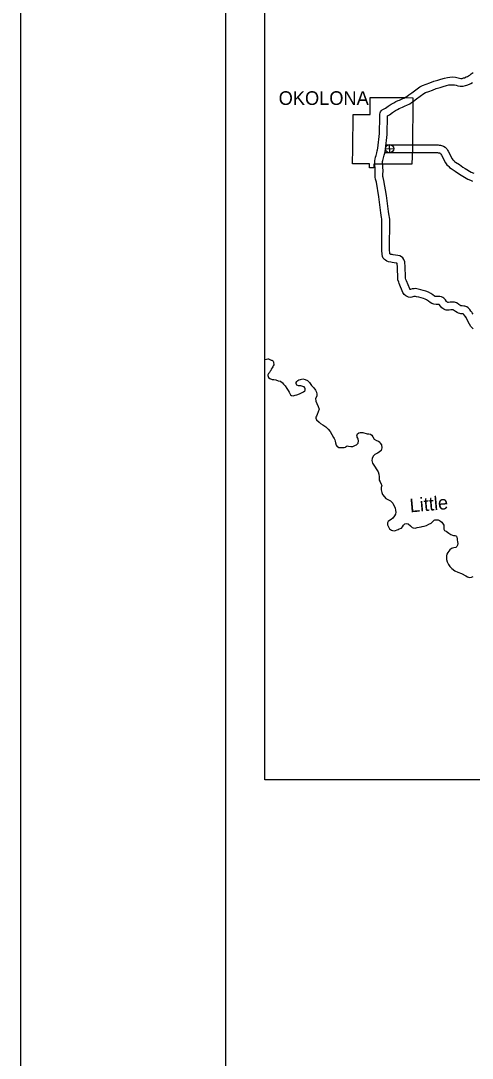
# Model space of a CAD drawing. Extents: x 1369979 to 1371646, y 379997 to 381064.
# Drawn here: x 1369978.9 to 1370115.6, y 380566.3 to 380880.1 of the extents above; entities that cross this region are included whole.
import ezdxf

# ---------------------------------------------------------------- set-up
doc = ezdxf.new("R2010")
doc.units = 0
for name, color, linetype in [('R_Border', 7, 'Continuous'), ('R_Border Notes', 7, 'Continuous'), ('R_No Plot', 7, 'Continuous')]:
    doc.layers.add(name, color=color, linetype=linetype)

msp = doc.modelspace()

# ---------------------------------------------------------------- linework, layer by layer
at = {"layer": 'R_Border'}
msp.add_line((1370040.95, 380017.3), (1370040.95, 381044.6), dxfattribs=at)
at = {"layer": 'R_Border Notes'}
for p, q in [((1370089.3, 380841.38), (1370091.84, 380841.44)), ((1370090.6, 380840.14), (1370090.54, 380842.68)), ((1370113.55, 380790.62), (1370113.66, 380790.46)), ((1370115.58, 380791.8), (1370115.47, 380791.95))]:
    msp.add_line(p, q, dxfattribs=at)
for points in [[(1370087.48, 380845.85), (1370087.57, 380851.24), (1370087.57, 380851.63), (1370087.58, 380851.88), (1370087.66, 380852.25), (1370087.82, 380852.57), (1370088.03, 380852.87), (1370088.36, 380853.17), (1370089.27, 380853.69), (1370090.16, 380854.26), (1370091.08, 380854.91), (1370091.81, 380855.31), (1370092.46, 380855.66), (1370093.11, 380855.95), (1370093.57, 380856.13), (1370094.38, 380856.53), (1370094.89, 380856.71), (1370095.41, 380856.96), (1370095.77, 380857.23), (1370096.39, 380857.67), (1370097.27, 380858.32), (1370099.69, 380860.15), (1370100.55, 380860.56), (1370101.6, 380860.92), (1370102.71, 380861.34), (1370103.96, 380861.8), (1370105.15, 380862.16), (1370106.08, 380862.45), (1370107.22, 380862.78), (1370108.13, 380862.99), (1370108.75, 380863.07), (1370109.45, 380863.11), (1370110.49, 380863.03), (1370111.28, 380862.89), (1370111.73, 380862.73), (1370112.08, 380862.69), (1370112.5, 380862.69), (1370112.94, 380862.8), (1370113.22, 380862.87), (1370113.76, 380863.11), (1370114.15, 380863.28), (1370114.47, 380863.44), (1370114.86, 380863.7), (1370115.26, 380864.03), (1370115.85, 380864.44)], [(1370089.83, 380845.81), (1370089.91, 380851.22), (1370089.91, 380851.36), (1370090.49, 380851.69), (1370091.47, 380852.32), (1370092.32, 380852.92), (1370092.92, 380853.25), (1370093.49, 380853.55), (1370094.01, 380853.79), (1370094.51, 380853.98), (1370095.29, 380854.37), (1370095.79, 380854.54), (1370096.64, 380854.96), (1370097.14, 380855.34), (1370097.76, 380855.77), (1370098.68, 380856.45), (1370100.91, 380858.13), (1370101.44, 380858.39), (1370102.4, 380858.72), (1370103.53, 380859.15), (1370104.7, 380859.58), (1370105.84, 380859.92), (1370106.75, 380860.21), (1370107.81, 380860.51), (1370108.54, 380860.68), (1370108.96, 380860.73), (1370109.43, 380860.76), (1370110.2, 380860.7), (1370110.69, 380860.61), (1370111.19, 380860.44), (1370111.94, 380860.34), (1370112.82, 380860.35), (1370113.5, 380860.53), (1370113.97, 380860.64), (1370114.71, 380860.97), (1370115.14, 380861.16), (1370115.63, 380861.4)], [(1370097.57, 380856.82), (1370097.46, 380841.31), (1370097.34, 380836.72), (1370094.72, 380836.72), (1370085.79, 380836.77), (1370085.77, 380835.6), (1370084.49, 380835.61), (1370084.51, 380836.78), (1370079.35, 380836.81), (1370079.43, 380841.49)], [(1370079.43, 380841.49), (1370079.51, 380851.77), (1370084.66, 380851.74), (1370084.7, 380856.89), (1370095, 380856.86), (1370097.57, 380856.82)], [(1370087, 380841.55), (1370087.49, 380845.96)], [(1370089.33, 380841.29), (1370089.82, 380845.7)], [(1370113.66, 380790.46), (1370113.35, 380790.84), (1370113.05, 380791.21), (1370112.86, 380791.42), (1370112.83, 380791.44), (1370112.77, 380791.45), (1370112.69, 380791.47), (1370112.45, 380791.49), (1370112.17, 380791.49), (1370111.82, 380791.51), (1370111.38, 380791.65), (1370111.02, 380791.84), (1370110.54, 380792.13), (1370110.2, 380792.34), (1370109.93, 380792.52), (1370109.77, 380792.64), (1370109.62, 380792.66), (1370109.39, 380792.66), (1370109.14, 380792.63), (1370108.62, 380792.56), (1370108.1, 380792.54), (1370107.7, 380792.61), (1370107.39, 380792.69), (1370106.96, 380792.84), (1370106.34, 380793.3), (1370105.94, 380793.74), (1370105.55, 380794.28), (1370105.52, 380794.31), (1370105.44, 380794.31), (1370104.66, 380794.31), (1370103.96, 380794.38), (1370103.37, 380794.56), (1370102.84, 380794.87), (1370102.3, 380795.27), (1370101.75, 380795.65), (1370101.31, 380795.91), (1370100.82, 380796.08), (1370100.14, 380796.29), (1370099.44, 380796.46), (1370098.74, 380796.64), (1370098.4, 380796.7), (1370098.28, 380796.72), (1370098.18, 380796.72), (1370097.89, 380796.67), (1370097.34, 380796.52), (1370096.83, 380796.42), (1370096.25, 380796.53), (1370095.86, 380796.68), (1370095.47, 380796.89), (1370094.94, 380797.35), (1370094.55, 380797.93), (1370093.49, 380800.61), (1370093.32, 380801.05), (1370093.07, 380801.78), (1370092.94, 380805.9), (1370092.89, 380806.42), (1370092.86, 380806.63), (1370092.83, 380806.72), (1370092.8, 380806.76), (1370092.58, 380806.82), (1370091.36, 380807.01), (1370090.94, 380807.04), (1370090.26, 380807.19), (1370089.76, 380807.41), (1370089.34, 380807.65), (1370088.98, 380807.94), (1370088.66, 380808.34), (1370088.43, 380808.82), (1370088.27, 380809.51), (1370088.2, 380810.61), (1370088.26, 380819.81), (1370088.21, 380820.19), (1370088.1, 380820.62), (1370087.88, 380822.05), (1370087.28, 380826.87), (1370086.55, 380831.31), (1370086.31, 380832.21), (1370086.23, 380832.75), (1370086.16, 380833.7), (1370086.22, 380834.62), (1370086.08, 380837.32), (1370086.13, 380837.81), (1370086.17, 380838.2), (1370086.29, 380838.85), (1370086.46, 380839.35), (1370086.66, 380840.12), (1370086.84, 380840.72), (1370086.93, 380841.04), (1370087, 380841.57)], [(1370115.47, 380791.95), (1370115.17, 380792.31), (1370114.83, 380792.74), (1370114.36, 380793.26), (1370113.91, 380793.53), (1370113.62, 380793.64), (1370113.35, 380793.73), (1370112.98, 380793.8), (1370112.57, 380793.83), (1370112.26, 380793.84), (1370112.16, 380793.89), (1370111.78, 380794.12), (1370111.48, 380794.31), (1370111.27, 380794.44), (1370110.77, 380794.82), (1370110.24, 380794.94), (1370109.76, 380795.01), (1370109.22, 380795), (1370108.85, 380794.95), (1370108.42, 380794.9), (1370108.28, 380794.89), (1370108.2, 380794.91), (1370108.06, 380794.94), (1370107.92, 380795.04), (1370107.76, 380795.22), (1370107.44, 380795.66), (1370107.26, 380795.9), (1370106.98, 380796.19), (1370106.63, 380796.38), (1370106.26, 380796.56), (1370105.78, 380796.66), (1370105.43, 380796.66), (1370104.77, 380796.65), (1370104.44, 380796.69), (1370104.32, 380796.72), (1370104.12, 380796.84), (1370103.65, 380797.18), (1370103.02, 380797.62), (1370102.3, 380798.05), (1370101.55, 380798.3), (1370100.77, 380798.55), (1370100, 380798.74), (1370099.25, 380798.92), (1370098.81, 380799.01), (1370098.42, 380799.07), (1370097.97, 380799.06), (1370097.38, 380798.97), (1370096.85, 380798.81), (1370096.81, 380798.83), (1370096.71, 380798.92), (1370096.64, 380799.02), (1370095.67, 380801.47), (1370095.52, 380801.86), (1370095.4, 380802.21), (1370095.28, 380806.04), (1370095.22, 380806.71), (1370095.14, 380807.18), (1370094.98, 380807.66), (1370094.83, 380807.94), (1370094.6, 380808.35), (1370094.15, 380808.74), (1370093.64, 380808.97), (1370093.06, 380809.12), (1370091.63, 380809.34), (1370091.3, 380809.37), (1370090.98, 380809.44), (1370090.81, 380809.51), (1370090.67, 380809.59), (1370090.66, 380809.6), (1370090.6, 380809.86), (1370090.54, 380810.69), (1370090.61, 380819.98), (1370090.51, 380820.65), (1370090.4, 380821.08), (1370090.2, 380822.37), (1370089.6, 380827.21), (1370088.85, 380831.81), (1370088.61, 380832.69), (1370088.56, 380833), (1370088.51, 380833.71), (1370088.57, 380834.61), (1370088.43, 380837.26), (1370088.46, 380837.56), (1370088.49, 380837.85), (1370088.57, 380838.26), (1370088.71, 380838.67), (1370088.92, 380839.48), (1370089.09, 380840.06), (1370089.24, 380840.58), (1370089.33, 380841.27)], [(1370089.5, 380842.59), (1370103.42, 380842.55), (1370104.28, 380842.58), (1370104.7, 380842.55), (1370105.24, 380842.55), (1370105.6, 380842.51), (1370106.01, 380842.45), (1370106.24, 380842.39), (1370106.54, 380842.3), (1370106.9, 380842.15), (1370107.36, 380841.88), (1370107.88, 380841.33), (1370108.08, 380840.99), (1370108.29, 380840.67), (1370109.47, 380838.36), (1370109.72, 380838.05), (1370109.88, 380837.87), (1370110.06, 380837.72), (1370110.2, 380837.57), (1370110.48, 380837.38), (1370111.69, 380836.58), (1370112.76, 380835.83), (1370113.48, 380835.37), (1370115.28, 380834.31), (1370116.02, 380833.97)], [(1370089.19, 380840.24), (1370103.46, 380840.21), (1370104.23, 380840.24), (1370104.61, 380840.21), (1370105.1, 380840.21), (1370105.3, 380840.18), (1370105.55, 380840.15), (1370105.62, 380840.13), (1370105.75, 380840.09), (1370105.84, 380840.05), (1370105.88, 380840.03), (1370106, 380839.91), (1370106.1, 380839.74), (1370106.27, 380839.48), (1370107.49, 380837.09), (1370107.93, 380836.53), (1370108.25, 380836.19), (1370108.45, 380836.01), (1370108.71, 380835.75), (1370109.18, 380835.44), (1370110.37, 380834.64), (1370111.46, 380833.87), (1370112.26, 380833.37), (1370114.2, 380832.22), (1370115.05, 380831.84), (1370115.7, 380831.55)], [(1370115.88, 380786.95), (1370115.14, 380787.62), (1370114.7, 380788.36), (1370114.38, 380789.02), (1370114.11, 380789.57), (1370113.77, 380790.23), (1370113.55, 380790.62)], [(1370115.84, 380791.35), (1370115.58, 380791.8)], [(1370052.8, 380777.61), (1370052.89, 380777.66), (1370053.31, 380777.78), (1370053.7, 380777.83), (1370053.92, 380777.88), (1370054.67, 380777.45), (1370054.9, 380777.44), (1370055.12, 380777.34), (1370055.15, 380777.3), (1370055.35, 380777.1), (1370055.43, 380776.84), (1370055.47, 380776.6), (1370055.5, 380776.25), (1370055.52, 380776), (1370055.34, 380775.75), (1370055.22, 380775.45), (1370055.06, 380775.15), (1370054.74, 380774.7), (1370054.57, 380774.35), (1370054.45, 380774.08), (1370054.33, 380773.87), (1370054.16, 380773.67), (1370054.05, 380773.54), (1370053.94, 380773.37), (1370053.8, 380773.11), (1370053.75, 380772.97), (1370053.75, 380772.77), (1370053.77, 380772.54), (1370053.92, 380772.15), (1370054.28, 380771.89), (1370055, 380771.59), (1370055.57, 380771.6), (1370056.1, 380771.5), (1370056.85, 380771.18), (1370057.49, 380771.09), (1370058.13, 380770.57), (1370058.47, 380770.21), (1370058.91, 380769.67), (1370059.47, 380768.85), (1370059.85, 380768.26), (1370060.13, 380767.71), (1370060.32, 380767.32), (1370060.58, 380766.98), (1370060.86, 380766.79), (1370061.42, 380766.69), (1370062.02, 380766.83), (1370062.46, 380766.92), (1370063.25, 380767.23), (1370063.7, 380767.45), (1370064.07, 380767.61), (1370064.5, 380767.87), (1370064.86, 380768.14), (1370065.01, 380768.37), (1370065, 380768.77), (1370064.86, 380769.1), (1370064.66, 380769.33), (1370064.33, 380769.5), (1370063.96, 380769.62), (1370063.67, 380769.68), (1370063.28, 380769.7), (1370062.96, 380769.71), (1370062.75, 380769.75), (1370062.53, 380769.89), (1370062.35, 380770.11), (1370062.24, 380770.38), (1370062.26, 380770.67), (1370062.44, 380770.97), (1370062.74, 380771.29), (1370063.08, 380771.5), (1370063.62, 380771.63), (1370064.25, 380771.77), (1370065, 380771.62), (1370065.68, 380771.24), (1370066.27, 380770.65), (1370066.95, 380769.82), (1370067.58, 380769.05), (1370068.1, 380768.36), (1370068.41, 380767.78), (1370068.49, 380767.13), (1370068.5, 380766.53), (1370068.12, 380765.83), (1370068.24, 380765.08), (1370068.58, 380764.37), (1370068.96, 380763.47), (1370069.22, 380762.59), (1370068.98, 380761.77), (1370068.63, 380761), (1370068.39, 380760.53), (1370068.23, 380760.21), (1370068.27, 380759.87), (1370068.45, 380759.4), (1370069.21, 380758.64), (1370069.68, 380758.3), (1370070.34, 380757.92), (1370071.31, 380757.24), (1370071.99, 380756.6), (1370072.58, 380755.85), (1370073.08, 380754.99)], [(1370073.08, 380754.99), (1370073.59, 380754.01), (1370073.79, 380753.73), (1370074, 380753.36), (1370074.06, 380752.89), (1370074.15, 380752.41), (1370074.34, 380751.77), (1370074.54, 380751.46), (1370074.8, 380751.28), (1370075.22, 380751.06), (1370075.98, 380751.05), (1370076.42, 380751.03), (1370076.78, 380751), (1370077.26, 380751.16), (1370077.42, 380751.32), (1370077.76, 380751.51), (1370078.16, 380751.46), (1370078.86, 380751.34), (1370079.45, 380751.33), (1370080.23, 380751.68), (1370080.55, 380751.87), (1370081, 380752.36), (1370081.14, 380753.02), (1370081.05, 380753.56), (1370080.92, 380753.83), (1370080.79, 380754.18), (1370080.71, 380754.45), (1370080.69, 380754.69), (1370080.85, 380755.11), (1370081.27, 380755.47), (1370081.69, 380755.53), (1370082.42, 380755.53), (1370083.76, 380755.2), (1370084.32, 380755.17), (1370084.82, 380755.03), (1370085.19, 380754.72), (1370085.52, 380754.26), (1370085.86, 380753.57), (1370086.59, 380753.15), (1370087.2, 380752.94), (1370087.57, 380752.63), (1370087.75, 380752.37), (1370088.08, 380751.82), (1370088.25, 380750.96), (1370087.98, 380750.13), (1370087.45, 380749.65), (1370086.85, 380749.33), (1370086.09, 380748.93), (1370085.57, 380748.35), (1370085.26, 380747.7), (1370085.17, 380747.05), (1370085.39, 380746.27), (1370085.99, 380745.37), (1370086.66, 380744.3), (1370087.06, 380743.7), (1370087.33, 380742.98), (1370087.39, 380742.13), (1370087.39, 380741.65), (1370087.44, 380741.15), (1370087.66, 380740.62), (1370088.03, 380739.89), (1370088.17, 380739.48), (1370088.05, 380738.9), (1370088.01, 380738.2), (1370088.2, 380737.38), (1370088.43, 380736.79), (1370089.05, 380736.05), (1370089.46, 380735.56), (1370090.2, 380735.15), (1370090.87, 380734.91), (1370091.49, 380734.17), (1370091.85, 380733.51), (1370092.22, 380732.73), (1370092.37, 380732.01), (1370092.48, 380731.41), (1370092.35, 380730.82), (1370092.05, 380730.34), (1370091.53, 380729.68), (1370091.04, 380729.27), (1370090.53, 380728.89), (1370090.13, 380728.62), (1370089.89, 380728.21), (1370089.95, 380727.61), (1370090.21, 380726.97), (1370090.52, 380726.45), (1370091.11, 380726.04), (1370091.42, 380725.95), (1370092.07, 380725.86), (1370093.15, 380726.25), (1370093.45, 380726.4), (1370094.15, 380726.66), (1370094.45, 380727.06), (1370094.74, 380727.56), (1370095.16, 380727.9), (1370095.61, 380728.01), (1370096.16, 380727.89), (1370096.85, 380727.37), (1370097.38, 380726.81), (1370097.71, 380726.67), (1370098.31, 380726.66), (1370098.89, 380726.83)], [(1370098.89, 380726.83), (1370100.07, 380727.01), (1370100.39, 380727.1), (1370101.05, 380727.19), (1370101.73, 380727.47), (1370102.43, 380727.84), (1370103.1, 380728.16), (1370103.44, 380728.4), (1370103.73, 380728.7), (1370104.04, 380729), (1370104.26, 380729.11), (1370104.66, 380729.16), (1370105.22, 380729.11), (1370105.62, 380728.98), (1370106.01, 380728.71), (1370106.38, 380728.41), (1370107.02, 380727.54), (1370107.02, 380727.24), (1370107.02, 380726.84), (1370107.01, 380726.53), (1370107, 380726.27), (1370107.22, 380725.94), (1370107.65, 380725.72), (1370108.11, 380725.36), (1370108.54, 380725.1), (1370108.79, 380724.95), (1370109.12, 380724.73), (1370109.59, 380724.5), (1370109.94, 380724.39), (1370110.33, 380724.42), (1370110.59, 380724.34), (1370110.8, 380724.21), (1370110.94, 380723.77), (1370110.97, 380723.61), (1370111.02, 380723.1), (1370111.15, 380722.48), (1370111.19, 380721.93), (1370111.12, 380721.51), (1370110.94, 380721.11), (1370110.62, 380720.75), (1370110.04, 380720.64), (1370109.62, 380720.56), (1370109.25, 380720.47), (1370108.79, 380720.03), (1370108.44, 380719.61), (1370108.15, 380719.29), (1370107.85, 380718.71), (1370107.75, 380718.29), (1370107.75, 380717.71), (1370107.77, 380717.14), (1370107.99, 380716.43), (1370108.4, 380715.64), (1370108.82, 380715.07), (1370109.4, 380714.4), (1370110.26, 380713.72), (1370111.22, 380713.29), (1370112.29, 380712.86), (1370113.68, 380712.19), (1370114.12, 380711.89), (1370114.42, 380711.75), (1370114.72, 380711.74), (1370115.35, 380711.8), (1370115.85, 380711.98)]]:
    msp.add_lwpolyline(points, dxfattribs=at)
msp.add_circle((1370090.57, 380841.41), 1.27, dxfattribs=at)
at = {"layer": 'R_No Plot'}
for points in [[(1369978.91, 381064.07), (1371645.61, 381064.07), (1371645.61, 379997.39), (1369978.91, 379997.39)], [(1370052.8, 381020.95), (1370474.58, 381020.95), (1370474.58, 380650.53), (1370052.8, 380650.53)]]:
    msp.add_lwpolyline(points, close=True, dxfattribs=at)

# ---------------------------------------------------------------- texts
at = {"layer": 'R_Border Notes'}
msp.add_text('OKOLONA', height=4.125, dxfattribs=at).set_placement((1370056.98, 380854.66))
msp.add_text('Little', height=4.125, rotation=5, dxfattribs=at).set_placement((1370096.81, 380731.38))

doc.saveas('drawing.dxf')
